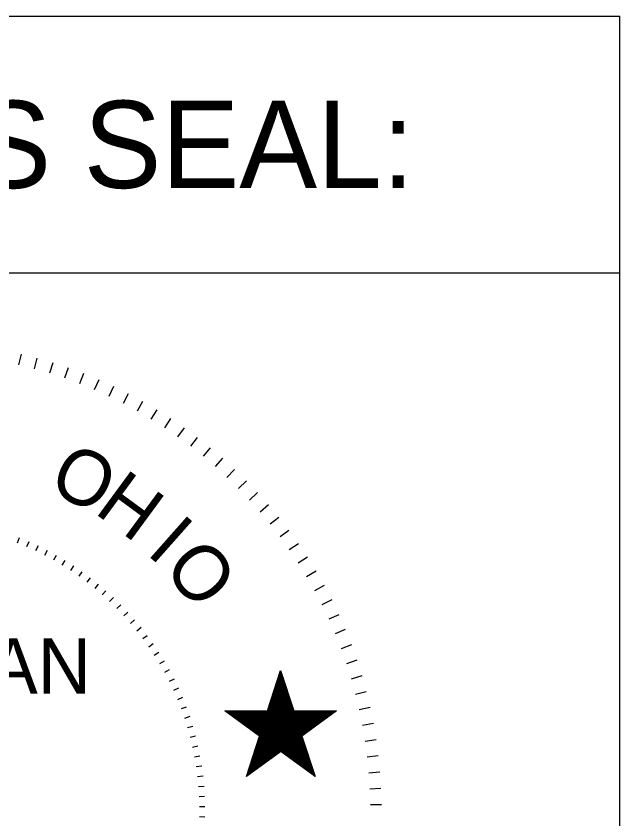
# Model space of a CAD drawing. Extents: x -10 to 89.7, y -4.8 to 22.
# Drawn here: x 10.073 to 11.25, y -3.15 to -1.586 of the extents above; entities that cross this region are included whole.
import ezdxf

# ---------------------------------------------------------------- set-up
doc = ezdxf.new("R2010")
doc.units = 0
doc.layers.add('GM_X_Minor_Lake', color=7, linetype='Continuous')
doc.layers.add('GM_X_Minor_River_Text', color=7, linetype='Continuous')

msp = doc.modelspace()

# ---------------------------------------------------------------- linework, layer by layer
at = {"layer": 'GM_X_Minor_Lake'}
for p, q in [((8.45, -1.5858), (11.25, -1.5858)), ((11.25, -4.8358), (11.25, -1.5858)), ((8.45, -2.0858), (11.25, -2.0858)), ((10.0833, -2.2442), (10.0784, -2.2651)), ((10.1142, -2.2521), (10.1086, -2.2729)), ((10.1448, -2.2611), (10.1384, -2.2816)), ((10.1751, -2.2711), (10.1679, -2.2915)), ((10.2049, -2.2822), (10.1971, -2.3022)), ((10.2344, -2.2944), (10.2259, -2.3141)), ((10.2634, -2.3075), (10.2542, -2.327)), ((10.2921, -2.3217), (10.2821, -2.3407)), ((10.3201, -2.3369), (10.3096, -2.3556)), ((10.3476, -2.353), (10.3363, -2.3714)), ((10.3744, -2.37), (10.3627, -2.388)), ((10.4008, -2.388), (10.3883, -2.4055)), ((10.4264, -2.4069), (10.4134, -2.424)), ((10.4514, -2.4267), (10.4378, -2.4434)), ((10.4757, -2.4474), (10.4614, -2.4635)), ((10.4992, -2.4689), (10.4844, -2.4845)), ((10.5221, -2.4911), (10.5067, -2.5062)), ((10.5441, -2.5142), (10.5282, -2.5287)), ((10.5652, -2.538), (10.5489, -2.552)), ((10.5856, -2.5626), (10.5687, -2.576)), ((10.6049, -2.5879), (10.5877, -2.6006)), ((10.0797, -2.6024), (10.0758, -2.6124)), ((10.0981, -2.61), (10.0938, -2.6197)), ((10.1162, -2.6181), (10.1116, -2.6279)), ((10.1339, -2.627), (10.1291, -2.6365)), ((10.6236, -2.6137), (10.6058, -2.6259)), ((10.1514, -2.6364), (10.1462, -2.6457)), ((10.6412, -2.6402), (10.6231, -2.6519)), ((10.1686, -2.6465), (10.1629, -2.6556)), ((10.1853, -2.6571), (10.1794, -2.6661)), ((10.2018, -2.6684), (10.1956, -2.6771)), ((10.6579, -2.6674), (10.6394, -2.6784)), ((10.2178, -2.6801), (10.2112, -2.6886)), ((10.2333, -2.6925), (10.2266, -2.7007)), ((10.2484, -2.7054), (10.2414, -2.7134)), ((10.6737, -2.6951), (10.6548, -2.7054)), ((10.2632, -2.7187), (10.2558, -2.7265)), ((10.2773, -2.7326), (10.2697, -2.7401)), ((10.6884, -2.7234), (10.6692, -2.733)), ((10.2911, -2.747), (10.2832, -2.7542)), ((10.7022, -2.7521), (10.6827, -2.761)), ((10.3043, -2.7619), (10.2962, -2.7689)), ((10.3169, -2.7771), (10.3086, -2.7839)), ((10.7149, -2.7812), (10.6952, -2.7895)), ((10.3291, -2.7929), (10.3204, -2.7992)), ((10.3407, -2.809), (10.3318, -2.8151)), ((10.7267, -2.8109), (10.7066, -2.8185)), ((10.3517, -2.8256), (10.3427, -2.8314)), ((10.3621, -2.8425), (10.3528, -2.848)), ((10.7374, -2.8409), (10.7171, -2.8477)), ((10.3719, -2.8597), (10.3624, -2.8649)), ((10.5634, -2.9396), (10.5889, -2.8606)), ((10.5883, -2.8626), (10.5892, -2.8616)), ((10.5889, -2.8606), (10.6146, -2.9396)), ((10.3812, -2.8774), (10.3716, -2.8822)), ((10.5784, -2.8934), (10.5944, -2.8774)), ((10.5792, -2.8906), (10.5938, -2.876)), ((10.5801, -2.8879), (10.5934, -2.8746)), ((10.5811, -2.885), (10.5929, -2.8731)), ((10.5819, -2.8822), (10.5924, -2.8717)), ((10.5829, -2.8795), (10.5921, -2.8702)), ((10.5838, -2.8766), (10.5916, -2.8687)), ((10.5846, -2.8739), (10.5911, -2.8674)), ((10.5856, -2.8711), (10.5907, -2.866)), ((10.5864, -2.8682), (10.5902, -2.8645)), ((10.5873, -2.8655), (10.5897, -2.8631)), ((10.7471, -2.8712), (10.7266, -2.8775)), ((10.5684, -2.9242), (10.5994, -2.8932)), ((10.5693, -2.9215), (10.5991, -2.8917)), ((10.5702, -2.9186), (10.5986, -2.8902)), ((10.5711, -2.9159), (10.5981, -2.8889)), ((10.5721, -2.9131), (10.5976, -2.8875)), ((10.5729, -2.9102), (10.5972, -2.886)), ((10.5738, -2.9075), (10.5967, -2.8846)), ((10.5747, -2.9046), (10.5962, -2.8832)), ((10.5756, -2.9019), (10.5958, -2.8817)), ((10.5766, -2.899), (10.5952, -2.8802)), ((10.5774, -2.8962), (10.5948, -2.8789)), ((10.3897, -2.8954), (10.3799, -2.8997)), ((10.5291, -2.975), (10.6022, -2.9017)), ((10.5302, -2.9757), (10.6028, -2.9031)), ((10.5312, -2.9766), (10.6032, -2.9046)), ((10.5323, -2.9774), (10.6036, -2.9061)), ((10.5334, -2.9781), (10.6042, -2.9075)), ((10.5346, -2.979), (10.6046, -2.909)), ((10.5639, -2.9382), (10.6018, -2.9004)), ((10.5648, -2.9354), (10.6013, -2.8989)), ((10.5657, -2.9326), (10.6008, -2.8975)), ((10.5667, -2.9299), (10.6004, -2.8961)), ((10.5676, -2.927), (10.5999, -2.8946)), ((10.7557, -2.902), (10.7349, -2.9074)), ((10.3977, -2.9135), (10.3878, -2.9176)), ((10.5357, -2.9797), (10.6051, -2.9104)), ((10.5367, -2.9806), (10.6056, -2.9117)), ((10.5379, -2.9814), (10.6059, -2.9132)), ((10.5389, -2.9822), (10.6064, -2.9146)), ((10.5401, -2.983), (10.6069, -2.9161)), ((10.5411, -2.9837), (10.6074, -2.9176)), ((10.5423, -2.9846), (10.6078, -2.919)), ((10.5433, -2.9854), (10.6083, -2.9205)), ((10.5444, -2.9862), (10.6088, -2.9219)), ((10.5456, -2.987), (10.6092, -2.9232)), ((10.5467, -2.9879), (10.6097, -2.9247)), ((10.4051, -2.932), (10.3949, -2.9357)), ((10.5477, -2.9886), (10.4803, -2.9396)), ((10.4803, -2.9396), (10.5634, -2.9396)), ((10.4807, -2.9399), (10.4809, -2.9396)), ((10.4817, -2.9406), (10.4829, -2.9396)), ((10.4829, -2.9414), (10.4847, -2.9396)), ((10.4839, -2.9422), (10.4867, -2.9396)), ((10.4851, -2.943), (10.4886, -2.9396)), ((10.4861, -2.9439), (10.4904, -2.9396)), ((10.4873, -2.9446), (10.4923, -2.9396)), ((10.4883, -2.9454), (10.4943, -2.9396)), ((10.4894, -2.9462), (10.4961, -2.9396)), ((10.4906, -2.947), (10.4981, -2.9396)), ((10.4917, -2.9479), (10.4999, -2.9396)), ((10.4928, -2.9486), (10.5018, -2.9396)), ((10.4938, -2.9495), (10.5037, -2.9396)), ((10.4949, -2.9502), (10.5057, -2.9396)), ((10.4961, -2.951), (10.5074, -2.9396)), ((10.4972, -2.9519), (10.5094, -2.9396)), ((10.4982, -2.9526), (10.5113, -2.9396)), ((10.4993, -2.9535), (10.5132, -2.9396)), ((10.5004, -2.9542), (10.5151, -2.9396)), ((10.5016, -2.9551), (10.5171, -2.9396)), ((10.5027, -2.9559), (10.5188, -2.9396)), ((10.5037, -2.9566), (10.5208, -2.9396)), ((10.5049, -2.9574), (10.5227, -2.9396)), ((10.5059, -2.9581), (10.5247, -2.9396)), ((10.5071, -2.959), (10.5264, -2.9396)), ((10.5082, -2.9597), (10.5284, -2.9396)), ((10.5092, -2.9606), (10.5303, -2.9396)), ((10.5104, -2.9614), (10.5322, -2.9396)), ((10.5114, -2.9622), (10.5341, -2.9396)), ((10.5126, -2.963), (10.5361, -2.9396)), ((10.5136, -2.9639), (10.5379, -2.9396)), ((10.5148, -2.9646), (10.5398, -2.9396)), ((10.5158, -2.9654), (10.5417, -2.9396)), ((10.5169, -2.9662), (10.5436, -2.9396)), ((10.5181, -2.967), (10.5456, -2.9396)), ((10.5192, -2.9679), (10.5474, -2.9396)), ((10.5203, -2.9686), (10.5493, -2.9396)), ((10.5213, -2.9695), (10.5512, -2.9396)), ((10.5224, -2.9702), (10.5532, -2.9396)), ((10.5224, -3.067), (10.6499, -2.9396)), ((10.5234, -3.0642), (10.6481, -2.9396)), ((10.5236, -2.971), (10.5549, -2.9396)), ((10.5242, -3.0614), (10.6462, -2.9396)), ((10.5247, -2.9719), (10.5569, -2.9396)), ((10.5252, -3.0586), (10.6442, -2.9396)), ((10.5257, -2.9726), (10.5588, -2.9396)), ((10.5261, -3.0559), (10.6424, -2.9396)), ((10.5268, -2.9734), (10.5607, -2.9396)), ((10.5269, -3.053), (10.6404, -2.9396)), ((10.5279, -2.9742), (10.5626, -2.9396)), ((10.5279, -3.0502), (10.6386, -2.9396)), ((10.5288, -3.0475), (10.6366, -2.9396)), ((10.5288, -3.0626), (10.6518, -2.9396)), ((10.5297, -3.0446), (10.6348, -2.9396)), ((10.5306, -3.0419), (10.6328, -2.9396)), ((10.5314, -3.0391), (10.6309, -2.9396)), ((10.5324, -3.0362), (10.6291, -2.9396)), ((10.5333, -3.0335), (10.6272, -2.9396)), ((10.5341, -3.0307), (10.6252, -2.9396)), ((10.5351, -3.0279), (10.6234, -2.9396)), ((10.5358, -3.0575), (10.6538, -2.9396)), ((10.5359, -3.025), (10.6214, -2.9396)), ((10.5369, -3.0222), (10.6196, -2.9396)), ((10.5378, -3.0194), (10.6177, -2.9396)), ((10.5387, -3.0166), (10.6158, -2.9396)), ((10.5396, -3.0139), (10.6143, -2.939)), ((10.5404, -3.011), (10.6139, -2.9376)), ((10.5414, -3.0082), (10.6134, -2.9361)), ((10.5423, -3.0055), (10.6129, -2.9347)), ((10.5429, -3.0522), (10.6556, -2.9396)), ((10.5432, -3.0026), (10.6126, -2.9334)), ((10.5441, -2.9999), (10.6121, -2.9319)), ((10.5449, -2.9971), (10.6116, -2.9305)), ((10.5459, -2.9942), (10.6112, -2.9291)), ((10.5468, -2.9915), (10.6106, -2.9276)), ((10.5477, -2.9887), (10.6102, -2.9261)), ((10.5499, -3.0472), (10.6576, -2.9396)), ((10.5569, -3.0421), (10.6594, -2.9396)), ((10.5639, -3.037), (10.6613, -2.9396)), ((10.5709, -3.0319), (10.6632, -2.9396)), ((10.5779, -3.0267), (10.6652, -2.9396)), ((10.5849, -3.0216), (10.6671, -2.9396)), ((10.5896, -3.019), (10.6689, -2.9396)), ((10.5907, -3.0197), (10.6708, -2.9396)), ((10.5917, -3.0206), (10.6727, -2.9396)), ((10.5929, -3.0214), (10.6747, -2.9396)), ((10.5939, -3.0222), (10.6766, -2.9396)), ((10.5951, -3.023), (10.6784, -2.9396)), ((10.6146, -2.9396), (10.6976, -2.9396)), ((10.6976, -2.9396), (10.6304, -2.9885)), ((10.6341, -2.9859), (10.6803, -2.9396)), ((10.6411, -2.9807), (10.6823, -2.9396)), ((10.6481, -2.9756), (10.6841, -2.9396)), ((10.6551, -2.9705), (10.6861, -2.9396)), ((10.6621, -2.9654), (10.6879, -2.9396)), ((10.6692, -2.9604), (10.6898, -2.9396)), ((10.6762, -2.9551), (10.6917, -2.9396)), ((10.6831, -2.95), (10.6937, -2.9396)), ((10.6901, -2.945), (10.6956, -2.9396)), ((10.6972, -2.9399), (10.6974, -2.9396)), ((10.7632, -2.933), (10.7422, -2.9376)), ((10.4117, -2.9507), (10.4016, -2.9541)), ((10.4177, -2.9696), (10.4074, -2.9727)), ((10.7696, -2.9641), (10.7484, -2.9681)), ((10.4231, -2.9887), (10.4127, -2.9915)), ((10.5224, -3.0672), (10.5477, -2.9886)), ((10.5961, -3.0237), (10.6307, -2.9892)), ((10.5973, -3.0246), (10.6311, -2.9906)), ((10.5983, -3.0254), (10.6316, -2.9921)), ((10.5994, -3.0261), (10.6321, -2.9935)), ((10.6006, -3.0269), (10.6326, -2.9949)), ((10.6017, -3.0277), (10.6329, -2.9964)), ((10.6028, -3.0285), (10.6334, -2.9979)), ((10.6038, -3.0294), (10.6339, -2.9992)), ((10.6049, -3.0301), (10.6343, -3.0007)), ((10.6059, -3.0309), (10.6349, -3.0021)), ((10.6304, -2.9885), (10.6561, -3.0672)), ((10.7749, -2.9956), (10.7537, -2.9989)), ((10.4277, -3.0081), (10.4173, -3.0105)), ((10.5891, -3.0186), (10.5224, -3.0672)), ((10.6561, -3.0672), (10.5891, -3.0186)), ((10.6072, -3.0317), (10.6353, -3.0035)), ((10.6082, -3.0325), (10.6357, -3.005)), ((10.6093, -3.0334), (10.6363, -3.0064)), ((10.6104, -3.0341), (10.6367, -3.0077)), ((10.6116, -3.035), (10.6372, -3.0094)), ((10.6127, -3.0357), (10.6377, -3.0107)), ((10.6137, -3.0365), (10.6381, -3.0121)), ((10.6148, -3.0374), (10.6386, -3.0136)), ((10.6159, -3.0381), (10.6391, -3.015)), ((10.6171, -3.039), (10.6396, -3.0164)), ((10.6182, -3.0397), (10.6399, -3.0179)), ((10.4317, -3.0276), (10.4212, -3.0295)), ((10.6192, -3.0406), (10.6404, -3.0192)), ((10.6204, -3.0414), (10.6409, -3.0207)), ((10.6214, -3.0421), (10.6413, -3.0222)), ((10.6226, -3.043), (10.6418, -3.0236)), ((10.6236, -3.0437), (10.6423, -3.0251)), ((10.6248, -3.0445), (10.6428, -3.0265)), ((10.6258, -3.0452), (10.6433, -3.0279)), ((10.6269, -3.0461), (10.6437, -3.0294)), ((10.6281, -3.0469), (10.6442, -3.0307)), ((10.6291, -3.0477), (10.6447, -3.0322)), ((10.6303, -3.0485), (10.6451, -3.0337)), ((10.7792, -3.0272), (10.7578, -3.0296)), ((10.4351, -3.0471), (10.4244, -3.0487)), ((10.6313, -3.0492), (10.6457, -3.0351)), ((10.6324, -3.0501), (10.6461, -3.0365)), ((10.6334, -3.0509), (10.6464, -3.038)), ((10.6347, -3.0517), (10.6471, -3.0394)), ((10.6357, -3.0525), (10.6474, -3.0407)), ((10.6368, -3.0534), (10.6479, -3.0422)), ((10.6379, -3.0541), (10.6484, -3.0437)), ((10.6391, -3.055), (10.6488, -3.0451)), ((10.6402, -3.0557), (10.6493, -3.0466)), ((10.6412, -3.0565), (10.6498, -3.048)), ((10.6423, -3.0574), (10.6502, -3.0494)), ((10.6434, -3.0581), (10.6507, -3.0509)), ((10.6446, -3.059), (10.6512, -3.0522)), ((10.6457, -3.0597), (10.6517, -3.0536)), ((10.6467, -3.0605), (10.6521, -3.0551)), ((10.6479, -3.0612), (10.6526, -3.0566)), ((10.6489, -3.062), (10.6531, -3.058)), ((10.6501, -3.0629), (10.6534, -3.0595)), ((10.6511, -3.0636), (10.6541, -3.0609)), ((10.6523, -3.0645), (10.6544, -3.0622)), ((10.6533, -3.0652), (10.6548, -3.0637)), ((10.6544, -3.0661), (10.6554, -3.0651)), ((10.7823, -3.0589), (10.7608, -3.0606)), ((10.4377, -3.0669), (10.4271, -3.0681)), ((10.6556, -3.0669), (10.6558, -3.0666)), ((10.4397, -3.0866), (10.4289, -3.0875)), ((10.7843, -3.0907), (10.7628, -3.0917)), ((10.4409, -3.1065), (10.4302, -3.107)), ((10.4414, -3.1264), (10.4307, -3.1265)), ((10.7852, -3.1226), (10.7637, -3.1227)), ((10.4413, -3.1462), (10.4306, -3.146))]:
    msp.add_line(p, q, dxfattribs=at)

# ---------------------------------------------------------------- texts
for s, rotation, p in [('O', 332.9745, (10.1323, -2.5079)), ('H', 323.6796, (10.2234, -2.5524)), ('I', 318.4511, (10.3252, -2.6324)), ('O', 310.6697, (10.3571, -2.6635))]:
    msp.add_text(s, height=0.1074, rotation=rotation, dxfattribs=at).set_placement(p)
msp.add_text('JONATHAN', height=0.10742, dxfattribs=at).set_placement((9.4453, -2.9056))
at = {"layer": 'GM_X_Minor_River_Text'}
msp.add_text("ENGINEER'S SEAL:", height=0.17, dxfattribs=at).set_placement((8.7595, -1.9208))

doc.saveas('drawing.dxf')
